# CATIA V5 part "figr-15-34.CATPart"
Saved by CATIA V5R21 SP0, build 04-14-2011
Part number: Part1
Bounding box of the stored display mesh (mm): x -40.264 to 42.014, y -25.445 to 25.445, z -51 to 0.75
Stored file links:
  D:\CATIA V5R21 E-RESOURCES\CATIA-V5R21\catia-v5r21-prt\c15-catia-v5r20-prt\c15-catia-v5r21-figr-15-34.CATPart
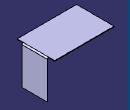
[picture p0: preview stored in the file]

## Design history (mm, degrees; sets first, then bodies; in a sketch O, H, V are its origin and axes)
SheetMetalParameters1: Thickness 0.75, BendRadius 1, KFactor 0.356492 {= log(min(100,max(20*SheetMetalParameters1.BendRadius,SheetMetalParameters1.Thickness)/SheetMetalParameters1.Thickness))/log(100)/2}, ReliefRadialLength 1, ReliefAxialLength 2, MinimumBendRadius 0
Body1 (main body)
  Sketch1 on xy-plane, origin (0, 0, 0), H (1, 0, 0), V (0, 1, 0)
    line L1 (-40.2643, 25.445) -> (40.2643, 25.445)
    line L2 (40.2643, 25.445) -> (40.2643, -25.445)
    line L3 (40.2643, -25.445) -> (-40.2643, -25.445)
    line L4 (-40.2643, -25.445) -> (-40.2643, 25.445)
    horizontal: L1 H, L3 H
    vertical: L2 V, L4 V
    symmetry: L1 L3 H, L4 L2 V
  Wall1: Thickness 0.75, Profile Sketch1
  Plane1: type Offset, RefPlane zx-plane, Offset 17
  Plane2: type Offset, RefPlane zx-plane, Offset 17, reversed
  Flange1: Angle 90, Length 50, Radius 1, KFacteur 0.356492 {= log(min(100,max(20*Flange1.Radius,SheetMetalParameters1.Thickness)/SheetMetalParameters1.Thickness))/log(100)/2}, Guide edge [face of Wall1 | face of Wall1], Limit1 Plane1, Limit2 Plane2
